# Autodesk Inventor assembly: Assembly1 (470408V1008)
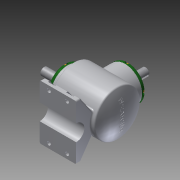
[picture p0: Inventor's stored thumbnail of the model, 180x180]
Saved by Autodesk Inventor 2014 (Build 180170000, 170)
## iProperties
Created: 2017-04
Part Number: Assembly1 (470408V1008)
Document SubType Name: Assembly
Designer: user
Author: user
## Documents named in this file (14)
- C:\Users\user\Desktop\470408V1008\Assembly1 (470408V1008).iam
- C:\Users\user\Desktop\470408V1008\1-본체 (470408V1008).ipt
- C:\Users\user\Desktop\470408V1008\커버.ipt
- C:\Users\user\Desktop\470408V1008\메인 축.ipt
- 메인 축.ipt
- C:\Users\user\Desktop\470408V1008\베어링 6203.ipt
- C:\Users\user\Desktop\470408V1008\키 5x5.ipt
- C:\Users\user\Desktop\470408V1008\서브 축.ipt
- 서브 축.ipt
- C:\Users\user\Desktop\470408V1008\키 4x4.ipt
- C:\Users\user\Desktop\470408V1008\오일실 17 32 8.ipt
- C:\Users\user\Desktop\470408V1008\볼트 M4.ipt
- C:\Users\user\Desktop\470408V1008\메인 베벨기어.ipt
- C:\Users\user\Desktop\470408V1008\서브 베벨기어.ipt
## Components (1 placed, 1 different names)
1. 1-본체 (470408V1008):1 — Mate:1, Mate:2, Mate:3, Mate:7, Mate:14, Mate:16, Mate:17, Mate:18, Mate:19
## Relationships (9: Mate 9)
- Mate:1: 1-본체 (470408V1008):1
- Mate:2: 1-본체 (470408V1008):1
- Mate:3: 1-본체 (470408V1008):1
- Mate:7: 1-본체 (470408V1008):1
- Mate:14: 1-본체 (470408V1008):1
- Mate:16: 1-본체 (470408V1008):1
- Mate:17: 1-본체 (470408V1008):1
- Mate:18: 1-본체 (470408V1008):1
- Mate:19: 1-본체 (470408V1008):1
